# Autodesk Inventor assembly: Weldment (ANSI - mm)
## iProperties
Length Units: 11269
Angle Units: 11283
Time Units: 11279
Mass Units: 11290
Length Display Precision: 3
Angle Display Precision: 2
Part Number: Weldment (ANSI - mm)
Document SubType Name: Weldment
Created: 2002-06
Designer: smithga
Created: 2002-08
Control State: 0
Master: False
Shininess: 64.0
Angle Units: 11279
Time Units: 11290
Mass Units: 11283
Compacted: True
Density: 0.0
Volumn: 0.0
Area: 0.0
PropertySet Name: Model Information
